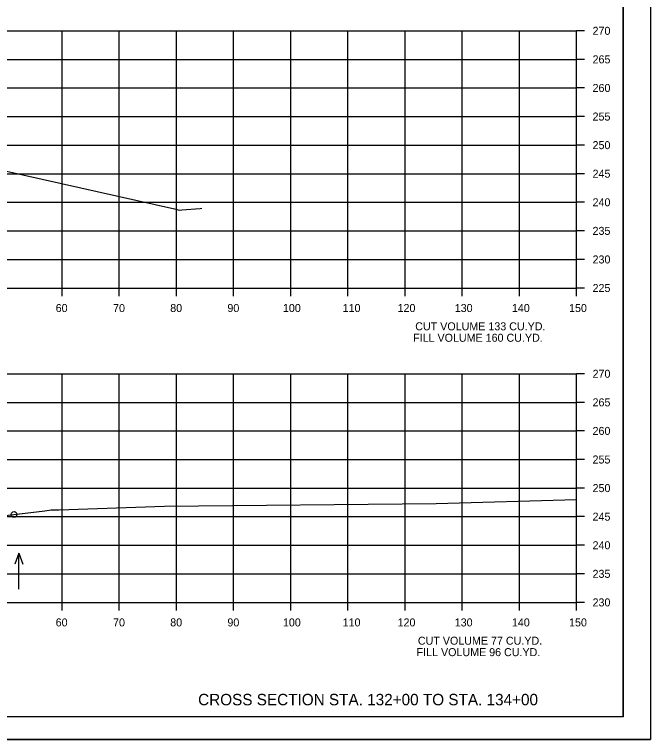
# Model space of a CAD drawing. Extents: x 1103485 to 1107180, y 2010593 to 2011873.
# Drawn here: x 1107068.9 to 1107180.1, y 2011446.2 to 2011573 of the extents above; entities that cross this region are included whole.
import ezdxf

# ---------------------------------------------------------------- set-up
doc = ezdxf.new("R2010")
doc.units = 0
for name, color, linetype in [('R_Axis', 7, 'Continuous'), ('R_Axis Annot', 7, 'Continuous'), ('R_Border', 7, 'Continuous'), ('R_Draft', 7, 'Continuous'), ('R_Exist Surface', 7, 'Continuous'), ('R_Grid', 7, 'Continuous'), ('R_No Plot', 7, 'Continuous'), ('R_Water Annot', 7, 'Continuous')]:
    doc.layers.add(name, color=color, linetype=linetype)

msp = doc.modelspace()

# ---------------------------------------------------------------- linework, layer by layer
at = {"layer": 'R_Axis'}
for p, q in [((1107167.18, 2011525.17), (1107167.18, 2011570.17)), ((1107168.58, 2011570.17), (1107167.18, 2011570.17)), ((1107168.58, 2011565.17), (1107167.18, 2011565.17)), ((1107168.58, 2011560.17), (1107167.18, 2011560.17)), ((1107168.58, 2011555.17), (1107167.18, 2011555.17)), ((1107168.58, 2011550.17), (1107167.18, 2011550.17)), ((1107168.58, 2011545.17), (1107167.18, 2011545.17)), ((1107168.58, 2011540.17), (1107167.18, 2011540.17)), ((1107168.58, 2011535.17), (1107167.18, 2011535.17)), ((1107168.58, 2011530.17), (1107167.18, 2011530.17)), ((1106867.18, 2011525.17), (1107167.18, 2011525.17)), ((1107077.18, 2011523.77), (1107077.18, 2011525.17)), ((1107087.18, 2011523.77), (1107087.18, 2011525.17)), ((1107097.18, 2011523.77), (1107097.18, 2011525.17)), ((1107107.18, 2011523.77), (1107107.18, 2011525.17)), ((1107117.18, 2011523.77), (1107117.18, 2011525.17)), ((1107127.18, 2011523.77), (1107127.18, 2011525.17)), ((1107137.18, 2011523.77), (1107137.18, 2011525.17)), ((1107147.18, 2011523.77), (1107147.18, 2011525.17)), ((1107157.18, 2011523.77), (1107157.18, 2011525.17)), ((1107167.18, 2011523.77), (1107167.18, 2011525.17)), ((1107168.58, 2011525.17), (1107167.18, 2011525.17)), ((1107167.18, 2011470.17), (1107167.18, 2011510.17)), ((1107168.58, 2011510.17), (1107167.18, 2011510.17)), ((1107168.58, 2011505.17), (1107167.18, 2011505.17)), ((1107168.58, 2011500.17), (1107167.18, 2011500.17)), ((1107168.58, 2011495.17), (1107167.18, 2011495.17)), ((1107168.58, 2011490.17), (1107167.18, 2011490.17)), ((1107168.58, 2011485.17), (1107167.18, 2011485.17)), ((1107168.58, 2011480.17), (1107167.18, 2011480.17)), ((1107168.58, 2011475.17), (1107167.18, 2011475.17)), ((1106867.18, 2011470.17), (1107167.18, 2011470.17)), ((1107077.18, 2011468.77), (1107077.18, 2011470.17)), ((1107087.18, 2011468.77), (1107087.18, 2011470.17)), ((1107097.18, 2011468.77), (1107097.18, 2011470.17)), ((1107107.18, 2011468.77), (1107107.18, 2011470.17)), ((1107117.18, 2011468.77), (1107117.18, 2011470.17)), ((1107127.18, 2011468.77), (1107127.18, 2011470.17)), ((1107137.18, 2011468.77), (1107137.18, 2011470.17)), ((1107147.18, 2011468.77), (1107147.18, 2011470.17)), ((1107157.18, 2011468.77), (1107157.18, 2011470.17)), ((1107167.18, 2011468.77), (1107167.18, 2011470.17)), ((1107168.58, 2011470.17), (1107167.18, 2011470.17))]:
    msp.add_line(p, q, dxfattribs=at)
at = {"layer": 'R_Border'}
for q in [(1107175.36, 2011655.63), (1106859.18, 2011450.17)]:
    msp.add_line((1107175.36, 2011450.17), q, dxfattribs=at)
at = {"layer": 'R_Exist Surface'}
for points in [[(1107066.93, 2011545.74), (1107096.83, 2011539), (1107097.7, 2011538.8), (1107098.13, 2011538.84), (1107101.33, 2011539.1), (1107101.64, 2011539.12)], [(1107063.73, 2011484.96), (1107074.14, 2011486.21), (1107075.24, 2011486.35), (1107075.92, 2011486.35), (1107076.67, 2011486.35), (1107095.09, 2011486.99), (1107142.64, 2011487.46), (1107167.18, 2011488.17)]]:
    msp.add_lwpolyline(points, dxfattribs=at)
at = {"layer": 'R_Grid'}
for p, q in [((1106867.18, 2011570.17), (1107167.18, 2011570.17)), ((1107077.18, 2011525.17), (1107077.18, 2011570.17)), ((1107087.18, 2011525.17), (1107087.18, 2011570.17)), ((1107097.18, 2011525.17), (1107097.18, 2011570.17)), ((1107107.18, 2011525.17), (1107107.18, 2011570.17)), ((1107117.18, 2011525.17), (1107117.18, 2011570.17)), ((1107127.18, 2011525.17), (1107127.18, 2011570.17)), ((1107137.18, 2011525.17), (1107137.18, 2011570.17)), ((1107147.18, 2011525.17), (1107147.18, 2011570.17)), ((1107157.18, 2011525.17), (1107157.18, 2011570.17)), ((1107167.18, 2011525.17), (1107167.18, 2011570.17)), ((1106867.18, 2011565.17), (1107167.18, 2011565.17)), ((1106867.18, 2011560.17), (1107167.18, 2011560.17)), ((1106867.18, 2011555.17), (1107167.18, 2011555.17)), ((1106867.18, 2011550.17), (1107167.18, 2011550.17)), ((1106867.18, 2011545.17), (1107167.18, 2011545.17)), ((1106867.18, 2011540.17), (1107167.18, 2011540.17)), ((1106867.18, 2011535.17), (1107167.18, 2011535.17)), ((1106867.18, 2011530.17), (1107167.18, 2011530.17)), ((1106867.18, 2011525.17), (1107167.18, 2011525.17)), ((1106867.18, 2011510.17), (1107167.18, 2011510.17)), ((1107077.18, 2011470.17), (1107077.18, 2011510.17)), ((1107087.18, 2011470.17), (1107087.18, 2011510.17)), ((1107097.18, 2011470.17), (1107097.18, 2011510.17)), ((1107107.18, 2011470.17), (1107107.18, 2011510.17)), ((1107117.18, 2011470.17), (1107117.18, 2011510.17)), ((1107127.18, 2011470.17), (1107127.18, 2011510.17)), ((1107137.18, 2011470.17), (1107137.18, 2011510.17)), ((1107147.18, 2011470.17), (1107147.18, 2011510.17)), ((1107157.18, 2011470.17), (1107157.18, 2011510.17)), ((1107167.18, 2011470.17), (1107167.18, 2011510.17)), ((1106867.18, 2011505.17), (1107167.18, 2011505.17)), ((1106867.18, 2011500.17), (1107167.18, 2011500.17)), ((1106867.18, 2011495.17), (1107167.18, 2011495.17)), ((1106867.18, 2011490.17), (1107167.18, 2011490.17)), ((1106867.18, 2011485.17), (1107167.18, 2011485.17)), ((1106867.18, 2011480.17), (1107167.18, 2011480.17)), ((1106867.18, 2011475.17), (1107167.18, 2011475.17)), ((1106867.18, 2011470.17), (1107167.18, 2011470.17))]:
    msp.add_line(p, q, dxfattribs=at)
at = {"layer": 'R_No Plot'}
msp.add_line((1106846.78, 2011446.19), (1107180.12, 2011446.19), dxfattribs=at)
for points in [[(1106846.78, 2011659.52), (1107180.12, 2011659.52), (1107180.12, 2011446.19), (1106846.78, 2011446.19)], [(1107093.1, 2011655.63), (1107093.1, 2011645.75), (1107128.84, 2011645.75), (1107128.84, 2011642.83), (1107152.04, 2011642.83), (1107152.04, 2011618.5), (1107175.36, 2011618.5), (1107175.36, 2011450.17), (1106859.18, 2011450.17), (1106859.18, 2011655.63)]]:
    msp.add_lwpolyline(points, close=True, dxfattribs=at)
msp.add_circle((1107068.77, 2011485.56), 0.5, dxfattribs=at)
at = {"layer": 'R_Water Annot'}
for p, q in [((1107069.63, 2011478.78), (1107068.93, 2011476.86)), ((1107069.63, 2011472.5), (1107069.63, 2011478.78)), ((1107069.63, 2011478.78), (1107070.33, 2011476.86))]:
    msp.add_line(p, q, dxfattribs=at)

# ---------------------------------------------------------------- texts
at = {"layer": 'R_Axis Annot'}
for s, p in [('270', (1107169.98, 2011569.47)), ('265', (1107169.98, 2011564.47)), ('260', (1107169.98, 2011559.47)), ('255', (1107169.98, 2011554.47)), ('250', (1107169.98, 2011549.47)), ('245', (1107169.98, 2011544.47)), ('240', (1107169.98, 2011539.47)), ('235', (1107169.98, 2011534.47)), ('230', (1107169.98, 2011529.47)), ('225', (1107169.98, 2011524.47)), ('60', (1107076.06, 2011520.97)), ('70', (1107086.1, 2011520.97)), ('80', (1107096.1, 2011520.97)), ('90', (1107106.1, 2011520.97)), ('100', (1107115.81, 2011520.97)), ('110', (1107126.26, 2011520.97)), ('120', (1107135.87, 2011520.97)), ('130', (1107145.87, 2011520.97)), ('140', (1107155.87, 2011520.97)), ('150', (1107165.87, 2011520.97)), ('CUT VOLUME 133 CU.YD.', (1107138.96, 2011517.77)), ('FILL VOLUME 160 CU.YD.', (1107138.59, 2011515.77)), ('270', (1107169.98, 2011509.47)), ('265', (1107169.98, 2011504.47)), ('260', (1107169.98, 2011499.47)), ('255', (1107169.98, 2011494.47)), ('250', (1107169.98, 2011489.47)), ('245', (1107169.98, 2011484.47)), ('240', (1107169.98, 2011479.47)), ('235', (1107169.98, 2011474.47)), ('230', (1107169.98, 2011469.47)), ('60', (1107076.06, 2011465.97)), ('70', (1107086.1, 2011465.97)), ('80', (1107096.1, 2011465.97)), ('90', (1107106.1, 2011465.97)), ('100', (1107115.81, 2011465.97)), ('110', (1107126.26, 2011465.97)), ('120', (1107135.87, 2011465.97)), ('130', (1107145.87, 2011465.97)), ('140', (1107155.87, 2011465.97)), ('150', (1107165.87, 2011465.97)), ('CUT VOLUME 77 CU.YD.', (1107139.42, 2011462.77)), ('FILL VOLUME 96 CU.YD.', (1107139.2, 2011460.77))]:
    msp.add_text(s, height=1.4, dxfattribs=at).set_placement(p)
at = {"layer": 'R_Draft'}
msp.add_text('CROSS SECTION STA. 132+00 TO STA. 134+00', height=2, dxfattribs=at).set_placement((1107100.98, 2011452.17))

doc.saveas('drawing.dxf')
